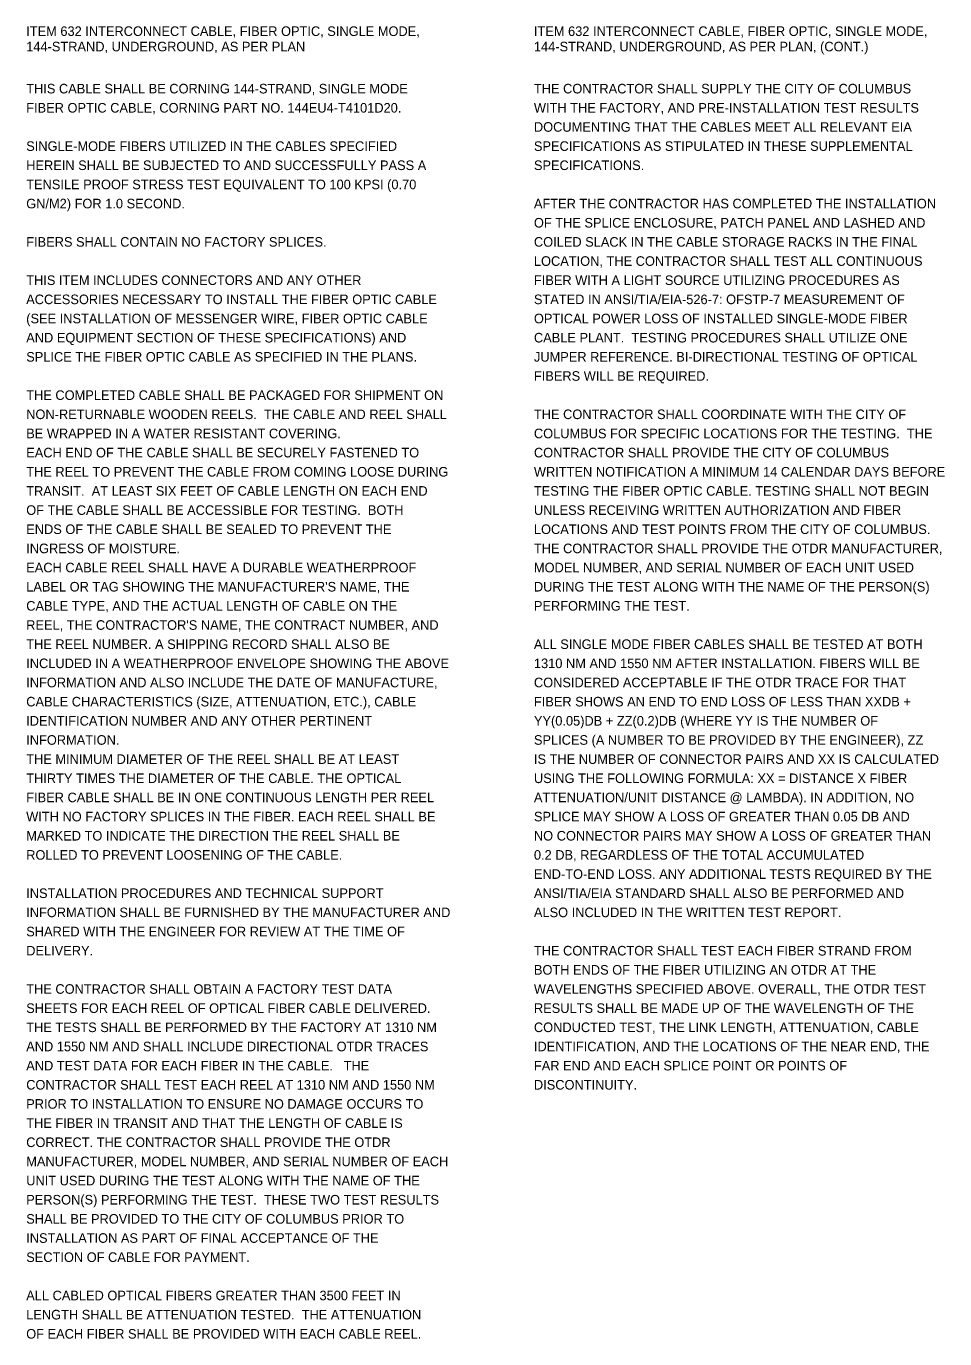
# Model space of a CAD drawing. Extents: x -15.1 to 53.7, y -46.4 to 36.
# Drawn here: x 2.39 to 15.82, y 16.77 to 35.96 of the extents above; entities that cross this region are included whole.
import ezdxf

# ---------------------------------------------------------------- set-up
doc = ezdxf.new("R2010")
doc.units = 0
doc.layers.add('SH_Data', color=7, linetype='Continuous')
doc.layers.add('SH_Text', color=7, linetype='Continuous')

msp = doc.modelspace()

# ---------------------------------------------------------------- texts
at = {"layer": 'SH_Data'}
for s, p in [('ITEM 632 INTERCONNECT CABLE, FIBER OPTIC, SINGLE MODE, ', (2.394, 35.816)), ('ITEM 632 INTERCONNECT CABLE, FIBER OPTIC, SINGLE MODE, ', (9.814, 35.816)), ('144-STRAND, UNDERGROUND, AS PER PLAN', (2.394, 35.591)), ('144-STRAND, UNDERGROUND, AS PER PLAN, (CONT.)', (9.814, 35.591)), ('THIS CABLE SHALL BE CORNING 144-STRAND, SINGLE MODE ', (2.394, 34.976)), ('FIBER OPTIC CABLE, CORNING PART NO. 144EU4-T4101D20.', (2.394, 34.696)), ('SINGLE-MODE FIBERS UTILIZED IN THE CABLES SPECIFIED ', (2.394, 34.136)), ('HEREIN SHALL BE SUBJECTED TO AND SUCCESSFULLY PASS A ', (2.394, 33.856)), ('TENSILE PROOF STRESS TEST EQUIVALENT TO 100 KPSI (0.70 ', (2.394, 33.576)), ('GN/M2) FOR 1.0 SECOND.', (2.394, 33.296)), ('FIBERS SHALL CONTAIN NO FACTORY SPLICES.', (2.394, 32.736)), ('THIS ITEM INCLUDES CONNECTORS AND ANY OTHER ', (2.394, 32.176)), ('ACCESSORIES NECESSARY TO INSTALL THE FIBER OPTIC CABLE ', (2.394, 31.896)), ('(SEE INSTALLATION OF MESSENGER WIRE, FIBER OPTIC CABLE ', (2.394, 31.616)), ('AND EQUIPMENT SECTION OF THESE SPECIFICATIONS) AND ', (2.394, 31.336)), ('SPLICE THE FIBER OPTIC CABLE AS SPECIFIED IN THE PLANS.', (2.394, 31.056)), ('THE COMPLETED CABLE SHALL BE PACKAGED FOR SHIPMENT ON ', (2.394, 30.496)), ('NON-RETURNABLE WOODEN REELS.  THE CABLE AND REEL SHALL ', (2.394, 30.216)), ('BE WRAPPED IN A WATER RESISTANT COVERING.', (2.394, 29.936)), ('EACH END OF THE CABLE SHALL BE SECURELY FASTENED TO ', (2.394, 29.656)), ('THE REEL TO PREVENT THE CABLE FROM COMING LOOSE DURING ', (2.394, 29.376)), ('TRANSIT.  AT LEAST SIX FEET OF CABLE LENGTH ON EACH END ', (2.394, 29.096)), ('OF THE CABLE SHALL BE ACCESSIBLE FOR TESTING.  BOTH ', (2.394, 28.816)), ('ENDS OF THE CABLE SHALL BE SEALED TO PREVENT THE ', (2.394, 28.536)), ('INGRESS OF MOISTURE.', (2.394, 28.256)), ('EACH CABLE REEL SHALL HAVE A DURABLE WEATHERPROOF ', (2.394, 27.976)), ("LABEL OR TAG SHOWING THE MANUFACTURER'S NAME, THE ", (2.394, 27.696)), ('CABLE TYPE, AND THE ACTUAL LENGTH OF CABLE ON THE ', (2.394, 27.416)), ("REEL, THE CONTRACTOR'S NAME, THE CONTRACT NUMBER, AND ", (2.394, 27.136)), ('THE REEL NUMBER. A SHIPPING RECORD SHALL ALSO BE ', (2.394, 26.856)), ('INCLUDED IN A WEATHERPROOF ENVELOPE SHOWING THE ABOVE ', (2.394, 26.576)), ('INFORMATION AND ALSO INCLUDE THE DATE OF MANUFACTURE, ', (2.394, 26.296)), ('CABLE CHARACTERISTICS (SIZE, ATTENUATION, ETC.), CABLE ', (2.394, 26.016)), ('IDENTIFICATION NUMBER AND ANY OTHER PERTINENT ', (2.394, 25.736)), ('INFORMATION.', (2.394, 25.456)), ('THE MINIMUM DIAMETER OF THE REEL SHALL BE AT LEAST ', (2.394, 25.176)), ('THIRTY TIMES THE DIAMETER OF THE CABLE. THE OPTICAL ', (2.394, 24.896)), ('FIBER CABLE SHALL BE IN ONE CONTINUOUS LENGTH PER REEL ', (2.394, 24.616)), ('WITH NO FACTORY SPLICES IN THE FIBER. EACH REEL SHALL BE ', (2.394, 24.336)), ('MARKED TO INDICATE THE DIRECTION THE REEL SHALL BE ', (2.394, 24.056)), ('ROLLED TO PREVENT LOOSENING OF THE CABLE.', (2.394, 23.776)), ('INSTALLATION PROCEDURES AND TECHNICAL SUPPORT ', (2.394, 23.216)), ('INFORMATION SHALL BE FURNISHED BY THE MANUFACTURER AND ', (2.394, 22.936)), ('SHARED WITH THE ENGINEER FOR REVIEW AT THE TIME OF ', (2.394, 22.656)), ('DELIVERY.', (2.394, 22.376)), ('THE CONTRACTOR SHALL OBTAIN A FACTORY TEST DATA ', (2.394, 21.816)), ('SHEETS FOR EACH REEL OF OPTICAL FIBER CABLE DELIVERED.  ', (2.394, 21.536)), ('THE TESTS SHALL BE PERFORMED BY THE FACTORY AT 1310 NM ', (2.394, 21.256)), ('AND 1550 NM AND SHALL INCLUDE DIRECTIONAL OTDR TRACES ', (2.394, 20.976)), ('AND TEST DATA FOR EACH FIBER IN THE CABLE.   THE ', (2.394, 20.696)), ('CONTRACTOR SHALL TEST EACH REEL AT 1310 NM AND 1550 NM ', (2.394, 20.416)), ('PRIOR TO INSTALLATION TO ENSURE NO DAMAGE OCCURS TO ', (2.394, 20.136)), ('THE FIBER IN TRANSIT AND THAT THE LENGTH OF CABLE IS ', (2.394, 19.856)), ('CORRECT. THE CONTRACTOR SHALL PROVIDE THE OTDR ', (2.394, 19.576)), ('MANUFACTURER, MODEL NUMBER, AND SERIAL NUMBER OF EACH ', (2.394, 19.296)), ('UNIT USED DURING THE TEST ALONG WITH THE NAME OF THE ', (2.394, 19.016)), ('PERSON(S) PERFORMING THE TEST.  THESE TWO TEST RESULTS ', (2.394, 18.736)), ('SHALL BE PROVIDED TO THE CITY OF COLUMBUS PRIOR TO ', (2.394, 18.456)), ('INSTALLATION AS PART OF FINAL ACCEPTANCE OF THE ', (2.394, 18.176)), ('SECTION OF CABLE FOR PAYMENT.', (2.394, 17.896)), ('ALL CABLED OPTICAL FIBERS GREATER THAN 3500 FEET IN ', (2.394, 17.336)), ('LENGTH SHALL BE ATTENUATION TESTED.  THE ATTENUATION ', (2.394, 17.056)), ('OF EACH FIBER SHALL BE PROVIDED WITH EACH CABLE REEL.', (2.394, 16.776))]:
    msp.add_text(s, height=0.14, dxfattribs=at).set_placement(p)
at = {"layer": 'SH_Text'}
for s, p in [('THE CONTRACTOR SHALL SUPPLY THE CITY OF COLUMBUS ', (9.814, 34.976)), ('WITH THE FACTORY, AND PRE-INSTALLATION TEST RESULTS ', (9.814, 34.696)), ('DOCUMENTING THAT THE CABLES MEET ALL RELEVANT EIA ', (9.814, 34.416)), ('SPECIFICATIONS AS STIPULATED IN THESE SUPPLEMENTAL ', (9.814, 34.136)), ('SPECIFICATIONS.', (9.814, 33.856)), ('AFTER THE CONTRACTOR HAS COMPLETED THE INSTALLATION ', (9.814, 33.296)), ('OF THE SPLICE ENCLOSURE, PATCH PANEL AND LASHED AND ', (9.814, 33.016)), ('COILED SLACK IN THE CABLE STORAGE RACKS IN THE FINAL ', (9.814, 32.736)), ('LOCATION, THE CONTRACTOR SHALL TEST ALL CONTINUOUS ', (9.814, 32.456)), ('FIBER WITH A LIGHT SOURCE UTILIZING PROCEDURES AS ', (9.814, 32.176)), ('STATED IN ANSI/TIA/EIA-526-7: OFSTP-7 MEASUREMENT OF ', (9.814, 31.896)), ('OPTICAL POWER LOSS OF INSTALLED SINGLE-MODE FIBER ', (9.814, 31.616)), ('CABLE PLANT.  TESTING PROCEDURES SHALL UTILIZE ONE ', (9.814, 31.336)), ('JUMPER REFERENCE. BI-DIRECTIONAL TESTING OF OPTICAL ', (9.814, 31.056)), ('FIBERS WILL BE REQUIRED.', (9.814, 30.776)), ('THE CONTRACTOR SHALL COORDINATE WITH THE CITY OF ', (9.814, 30.216)), ('COLUMBUS FOR SPECIFIC LOCATIONS FOR THE TESTING.  THE ', (9.814, 29.936)), ('CONTRACTOR SHALL PROVIDE THE CITY OF COLUMBUS ', (9.814, 29.656)), ('WRITTEN NOTIFICATION A MINIMUM 14 CALENDAR DAYS BEFORE ', (9.814, 29.376)), ('TESTING THE FIBER OPTIC CABLE. TESTING SHALL NOT BEGIN ', (9.814, 29.096)), ('UNLESS RECEIVING WRITTEN AUTHORIZATION AND FIBER ', (9.814, 28.816)), ('LOCATIONS AND TEST POINTS FROM THE CITY OF COLUMBUS.  ', (9.814, 28.536)), ('THE CONTRACTOR SHALL PROVIDE THE OTDR MANUFACTURER, ', (9.814, 28.256)), ('MODEL NUMBER, AND SERIAL NUMBER OF EACH UNIT USED ', (9.814, 27.976)), ('DURING THE TEST ALONG WITH THE NAME OF THE PERSON(S) ', (9.814, 27.696)), ('PERFORMING THE TEST. ', (9.814, 27.416)), ('ALL SINGLE MODE FIBER CABLES SHALL BE TESTED AT BOTH ', (9.814, 26.856)), ('1310 NM AND 1550 NM AFTER INSTALLATION. FIBERS WILL BE ', (9.814, 26.576)), ('CONSIDERED ACCEPTABLE IF THE OTDR TRACE FOR THAT ', (9.814, 26.296)), ('FIBER SHOWS AN END TO END LOSS OF LESS THAN XXDB + ', (9.814, 26.016)), ('YY(0.05)DB + ZZ(0.2)DB (WHERE YY IS THE NUMBER OF ', (9.814, 25.736)), ('SPLICES (A NUMBER TO BE PROVIDED BY THE ENGINEER), ZZ ', (9.814, 25.456)), ('IS THE NUMBER OF CONNECTOR PAIRS AND XX IS CALCULATED ', (9.814, 25.176)), ('USING THE FOLLOWING FORMULA: XX = DISTANCE X FIBER ', (9.814, 24.896)), ('ATTENUATION/UNIT DISTANCE @ LAMBDA). IN ADDITION, NO ', (9.814, 24.616)), ('SPLICE MAY SHOW A LOSS OF GREATER THAN 0.05 DB AND ', (9.814, 24.336)), ('NO CONNECTOR PAIRS MAY SHOW A LOSS OF GREATER THAN ', (9.814, 24.056)), ('0.2 DB, REGARDLESS OF THE TOTAL ACCUMULATED ', (9.814, 23.776)), ('END-TO-END LOSS. ANY ADDITIONAL TESTS REQUIRED BY THE ', (9.814, 23.496)), ('ANSI/TIA/EIA STANDARD SHALL ALSO BE PERFORMED AND ', (9.814, 23.216)), ('ALSO INCLUDED IN THE WRITTEN TEST REPORT.', (9.814, 22.936)), ('THE CONTRACTOR SHALL TEST EACH FIBER STRAND FROM ', (9.814, 22.376)), ('BOTH ENDS OF THE FIBER UTILIZING AN OTDR AT THE ', (9.814, 22.096)), ('WAVELENGTHS SPECIFIED ABOVE. OVERALL, THE OTDR TEST ', (9.814, 21.816)), ('RESULTS SHALL BE MADE UP OF THE WAVELENGTH OF THE ', (9.814, 21.536)), ('CONDUCTED TEST, THE LINK LENGTH, ATTENUATION, CABLE ', (9.814, 21.256)), ('IDENTIFICATION, AND THE LOCATIONS OF THE NEAR END, THE ', (9.814, 20.976)), ('FAR END AND EACH SPLICE POINT OR POINTS OF ', (9.814, 20.696)), ('DISCONTINUITY. ', (9.814, 20.416))]:
    msp.add_text(s, height=0.14, dxfattribs=at).set_placement(p)

doc.saveas('drawing.dxf')
